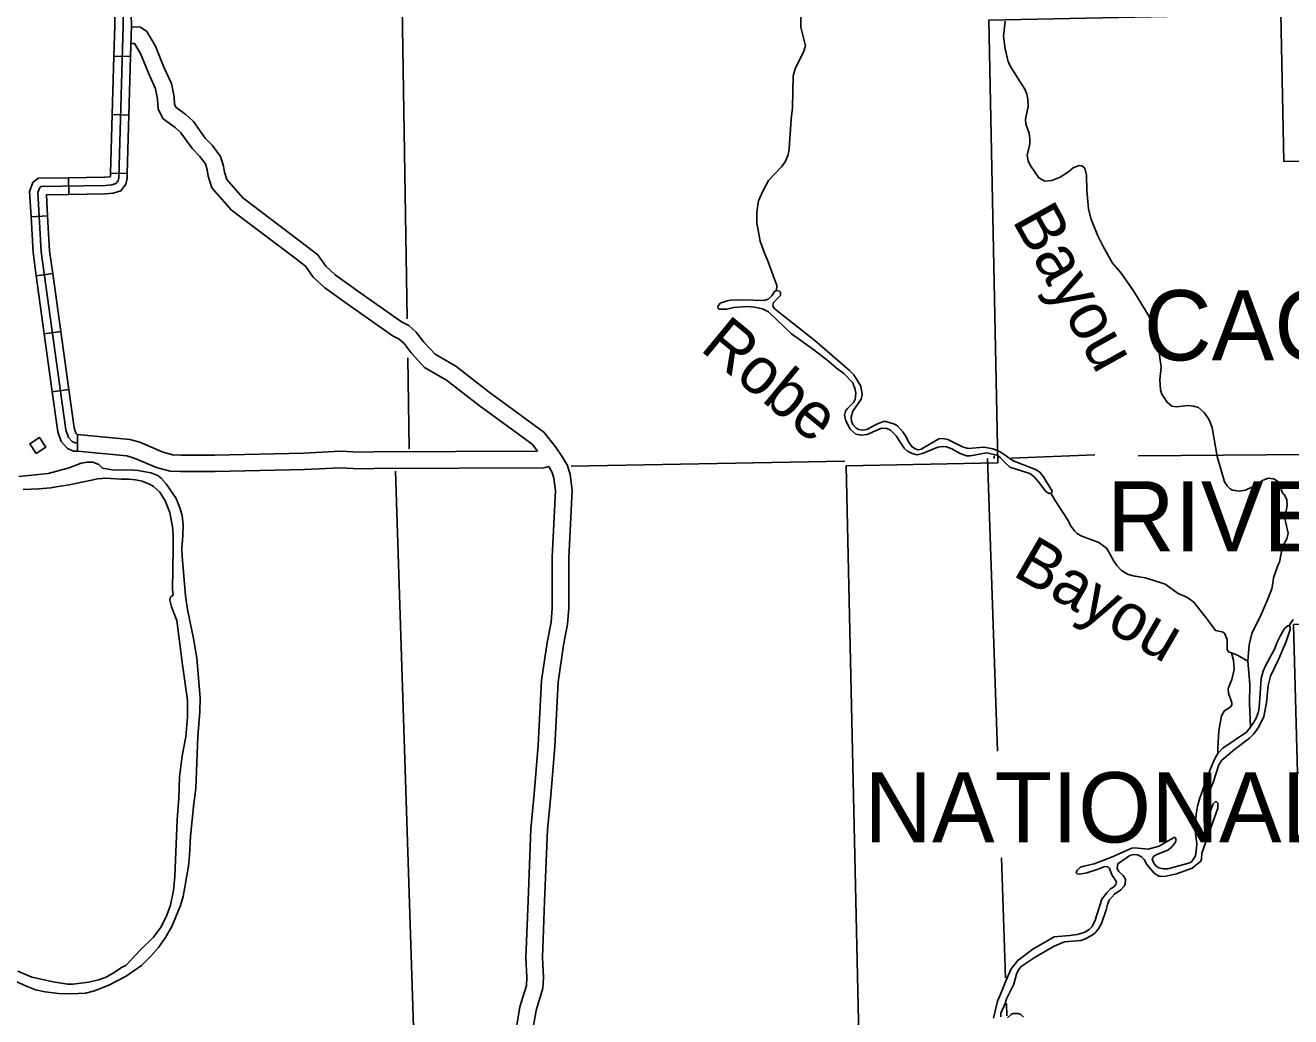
# Model space of a CAD drawing. Extents: x 1084508 to 1142749, y 1057638 to 1093403.
# Drawn here: x 1090132 to 1093716, y 1065503 to 1068310 of the extents above; entities that cross this region are included whole.
import ezdxf

# ---------------------------------------------------------------- set-up
doc = ezdxf.new("R2010")
doc.units = 0
for name, color, linetype in [('Level 32', 7, 'Continuous'), ('Level 35', 7, 'Continuous'), ('Level 4', 7, 'Continuous'), ('Level 46', 7, 'Continuous'), ('Level 5', 7, 'Continuous'), ('Level 56', 7, 'Continuous'), ('Level 7', 7, 'Continuous'), ('Level 9', 7, 'Continuous')]:
    doc.layers.add(name, color=color, linetype=linetype)

msp = doc.modelspace()

# ---------------------------------------------------------------- linework, layer by layer
at = {"layer": 'Level 32'}
for p, q in [((1090430.4, 1068221.7), (1090383.4, 1068223.1)), ((1090425.7, 1068056.1), (1090378.6, 1068057.4)), ((1090421, 1067890.4), (1090373.9, 1067891.8)), ((1090255.6, 1067831.5), (1090254.8, 1067878.5)), ((1090195.5, 1067770.4), (1090148.5, 1067767.7)), ((1090210, 1067607.3), (1090163.4, 1067600.8)), ((1090232.8, 1067443.1), (1090186.2, 1067436.7)), ((1090255.6, 1067279), (1090208.9, 1067272.5)), ((1090280.3, 1067151.7), (1090279.9, 1067104.6))]:
    msp.add_line(p, q, dxfattribs=at)
for points in [[(1090280.1, 1067128.2), (1090273.5, 1067128.2), (1090265.5, 1067131.4), (1090255, 1067143.5), (1090247.6, 1067164.9), (1090177.7, 1067669.1), (1090168.1, 1067836.7), (1090173.2, 1067850.7), (1090177.1, 1067853.7), (1090358.2, 1067856.7), (1090377, 1067858.4), (1090389, 1067862), (1090395, 1067870.1), (1090397.1, 1067879.6), (1090409.4, 1068309.7), (1090407.2, 1068407.1)], [(1090383.4, 1068223.1), (1090385.8, 1068309.8), (1090384.6, 1068366.1)], [(1090430.4, 1068221.7), (1090432.9, 1068309.6), (1090431.6, 1068369.5)], [(1090378.6, 1068057.4), (1090383.4, 1068223.1)], [(1090425.7, 1068056.1), (1090430.4, 1068221.7)], [(1090373.9, 1067891.8), (1090378.6, 1068057.4)], [(1090421, 1067890.4), (1090425.7, 1068056.1)], [(1090254.8, 1067878.5), (1090357, 1067880.2), (1090372.5, 1067881.6), (1090373.5, 1067881.9), (1090373.7, 1067882.6), (1090373.9, 1067891.8)], [(1090255.6, 1067831.5), (1090359.5, 1067833.2), (1090381.4, 1067835.2), (1090403.3, 1067841.7), (1090416.9, 1067860.1), (1090420.6, 1067876.7), (1090421, 1067890.4)], [(1090148.5, 1067767.7), (1090144.3, 1067840.2), (1090153.4, 1067865.3), (1090169.1, 1067877.1), (1090254.8, 1067878.5)], [(1090195.5, 1067770.4), (1090192, 1067830.4), (1090255.6, 1067831.5)], [(1090163.4, 1067600.8), (1090154.2, 1067666.8), (1090148.5, 1067767.7)], [(1090210, 1067607.3), (1090201.1, 1067671.4), (1090195.5, 1067770.4)], [(1090186.2, 1067436.7), (1090163.4, 1067600.8)], [(1090232.8, 1067443.1), (1090210, 1067607.3)], [(1090208.9, 1067272.5), (1090186.2, 1067436.7)], [(1090255.6, 1067279), (1090232.8, 1067443.1)], [(1090280.3, 1067151.7), (1090279.1, 1067151.7), (1090275.8, 1067155.5), (1090270.6, 1067170.5), (1090255.6, 1067279)], [(1090279.9, 1067104.6), (1090268.9, 1067104.7), (1090251.5, 1067111.6), (1090234.3, 1067131.6), (1090224.6, 1067159.4), (1090208.9, 1067272.5)]]:
    msp.add_lwpolyline(points, dxfattribs=at)
at = {"layer": 'Level 35'}
for points in [[(1092329.3, 1068346.6), (1092328.7, 1068305.4), (1092342, 1068252.3), (1092337, 1068234.3), (1092313.6, 1068190.1), (1092306.8, 1068167.6), (1092305.3, 1068077), (1092301.3, 1068045.1), (1092296.2, 1067960.3), (1092293, 1067943.2), (1092284.3, 1067923.4), (1092274.4, 1067909.6), (1092237, 1067871.3), (1092221.1, 1067840.9), (1092209.1, 1067813.5), (1092204.5, 1067780.9), (1092204.6, 1067750.1), (1092214.1, 1067698.9), (1092225.1, 1067667.8), (1092236.9, 1067640.2), (1092261.4, 1067573.1), (1092259.6, 1067559.8)], [(1092908.2, 1068322.1), (1092902.7, 1068279.5), (1092907.9, 1068243.5), (1092916.6, 1068207.3), (1092925.3, 1068189.4), (1092963.3, 1068129.9), (1092969.1, 1068115), (1092972, 1068101), (1092972.7, 1068080.3), (1092965.7, 1068045.1), (1092966.2, 1068030.7), (1092975.4, 1068004.9), (1092977.8, 1067989.9), (1092977.3, 1067975.1), (1092969.6, 1067943.1), (1092972.6, 1067926.8), (1092979, 1067914.8), (1093002.7, 1067878.1), (1093020.5, 1067869.3), (1093040.2, 1067870.9), (1093063.1, 1067880.7), (1093087.1, 1067895.7), (1093099.9, 1067907.1), (1093117.2, 1067913.6), (1093124.5, 1067912), (1093133.4, 1067905.4), (1093138.5, 1067885.7), (1093138.9, 1067842.7), (1093144, 1067790.6), (1093150.5, 1067763.2), (1093170.3, 1067713.8), (1093184.1, 1067685.7), (1093211.3, 1067636.9), (1093236.1, 1067608.4), (1093271.2, 1067558), (1093315.8, 1067485.9), (1093328.9, 1067448), (1093335.3, 1067416.8), (1093341.6, 1067395.6), (1093349.3, 1067342.7), (1093345.4, 1067306.4), (1093347.3, 1067277.9), (1093351.4, 1067266)], [(1093039.8, 1066986.4), (1093032.7, 1066984.3), (1093022.8, 1066990.2), (1093002.1, 1067017.5), (1092989.1, 1067032.2), (1092977.6, 1067040.9), (1092921.2, 1067058.9), (1092902.8, 1067075.6), (1092893.7, 1067086), (1092885, 1067093.2), (1092855, 1067099.8), (1092809.5, 1067091.4), (1092798, 1067091.3), (1092779.9, 1067098), (1092756.3, 1067111.3), (1092742, 1067116.2), (1092730.1, 1067117.1), (1092717, 1067115.7), (1092674, 1067097.3), (1092658.1, 1067094.3), (1092644.5, 1067097.6), (1092631.4, 1067104.7), (1092621.5, 1067113.2), (1092599, 1067148), (1092582.5, 1067164.1), (1092572.4, 1067168.5), (1092557.3, 1067169.3), (1092516.5, 1067151.9), (1092499.7, 1067149.2), (1092485.1, 1067152.8), (1092469, 1067166.4), (1092456.6, 1067190.5), (1092453, 1067206.1), (1092455.8, 1067217.5), (1092461.2, 1067225.6), (1092478.2, 1067242.2), (1092482.9, 1067250.5), (1092485.2, 1067268.8), (1092483.3, 1067278.8), (1092476.4, 1067297.7), (1092450.8, 1067324.3), (1092429.3, 1067339.9), (1092407.3, 1067359.6), (1092365.6, 1067391.6), (1092302.4, 1067436.4), (1092237.4, 1067499), (1092220.8, 1067507.3), (1092198.1, 1067512.2), (1092177.1, 1067514.3), (1092138.3, 1067511.2), (1092119.3, 1067506.8), (1092099, 1067506.1), (1092095.1, 1067508.5), (1092094.3, 1067514.4), (1092100.9, 1067523.2), (1092117.4, 1067529), (1092130.1, 1067531.7), (1092164.9, 1067533.4), (1092224.8, 1067530.7), (1092236.3, 1067534.5), (1092247.2, 1067544.6), (1092254.4, 1067556.5), (1092259.6, 1067559.8)], [(1092259.6, 1067559.8), (1092268.4, 1067557.6), (1092271, 1067555.1), (1092271, 1067545.4), (1092251.9, 1067525.6), (1092249.3, 1067518.3), (1092251, 1067513.3), (1092256, 1067506.9), (1092274.9, 1067491.4), (1092368.8, 1067418.1), (1092466.8, 1067333), (1092478.8, 1067320.2), (1092498.9, 1067288.4), (1092502.8, 1067265), (1092499.8, 1067252), (1092476.5, 1067217.6), (1092471.4, 1067200.4), (1092472.4, 1067189.1), (1092476.7, 1067180.2), (1092485.5, 1067169.8), (1092492.9, 1067165.3), (1092503.3, 1067163.4), (1092516.1, 1067165.4), (1092544.7, 1067180.8), (1092563, 1067188), (1092569.8, 1067188.2), (1092594.5, 1067181.2), (1092603.1, 1067176.4), (1092618.1, 1067159), (1092627.7, 1067144.5), (1092634.1, 1067130.6), (1092643, 1067117.1), (1092653.2, 1067110.5), (1092661.7, 1067107.9), (1092670.1, 1067109.8), (1092719.7, 1067138.8), (1092731.5, 1067139.8), (1092745.1, 1067137.1), (1092758.5, 1067130.9), (1092786.8, 1067116.4), (1092802.9, 1067112.2), (1092847.6, 1067115.9), (1092873.8, 1067110.8), (1092893.5, 1067102.3), (1092929, 1067078.3), (1092942.7, 1067071.9), (1092993.5, 1067052.8), (1093005.7, 1067044.7), (1093016.4, 1067032.1), (1093040.6, 1066991.4), (1093039.8, 1066986.4)], [(1093351.4, 1067266), (1093366.6, 1067243), (1093380.1, 1067232.1), (1093393.3, 1067230.3), (1093424.8, 1067233.6), (1093441.5, 1067231.9), (1093455.4, 1067227.6), (1093471.5, 1067213.7), (1093484.4, 1067194.9), (1093494.5, 1067171.7), (1093507.8, 1067088.8), (1093528.6, 1067017.8), (1093536.2, 1067005.8), (1093544.6, 1066997.6), (1093551.6, 1066994), (1093570.5, 1066990.9), (1093588.6, 1066993.7), (1093610.2, 1067003.8), (1093636.9, 1067021.3), (1093652.7, 1067027.8), (1093667.5, 1067026.1), (1093678.3, 1067020.2), (1093685.8, 1067010.4), (1093690.2, 1066992.9), (1093694.5, 1066984.6), (1093699, 1066980.6), (1093705.7, 1066966.7), (1093706.6, 1066950), (1093699.9, 1066913.4), (1093709.4, 1066871.9), (1093705.8, 1066855.7), (1093696.4, 1066838.7), (1093692.6, 1066829.5), (1093684.4, 1066790.2), (1093680.4, 1066780.3), (1093667.4, 1066746), (1093666, 1066730.2), (1093662.7, 1066714.7), (1093649.2, 1066678.1), (1093631.6, 1066640.1), (1093606.3, 1066588), (1093598.9, 1066556), (1093595.4, 1066509.4), (1093600.6, 1066444.8), (1093599.8, 1066389.4), (1093602.9, 1066322.5)], [(1093548.5, 1066533.6), (1093540.3, 1066535.9), (1093536.3, 1066543), (1093536.4, 1066570.6), (1093528.9, 1066588.9), (1093522.2, 1066592.8), (1093503.3, 1066596.6), (1093482.9, 1066625.2), (1093441.8, 1066676.3), (1093421.9, 1066691.1), (1093397.4, 1066701.3), (1093360.5, 1066727.4), (1093323.5, 1066740), (1093304.5, 1066745.4), (1093269.9, 1066750.9), (1093254.3, 1066756.3), (1093237.7, 1066766.5), (1093224.1, 1066780.5), (1093215.9, 1066792.5), (1093203.5, 1066815.7), (1093194.3, 1066829.2), (1093173.1, 1066845.8), (1093125.2, 1066863.4), (1093112.8, 1066870.5), (1093104.1, 1066878.4), (1093094.6, 1066890.7), (1093084.5, 1066910.5), (1093047.3, 1066967.1), (1093037.3, 1066985)], [(1093329.9, 1065935.3), (1093335.7, 1065928.9), (1093343.4, 1065923.8), (1093355.7, 1065921.4), (1093368.2, 1065921.8), (1093430.4, 1065938.6), (1093436.2, 1065942.6), (1093445.8, 1065956.4), (1093448.1, 1065962.5), (1093450.3, 1065991.8), (1093445.9, 1066029.4), (1093448.8, 1066076.6), (1093452.5, 1066099.1), (1093458.1, 1066118.7), (1093480.8, 1066184.3), (1093500.2, 1066231.7), (1093510.4, 1066247.8), (1093524.6, 1066262.7), (1093590.9, 1066308.3), (1093602.9, 1066322.5), (1093617.5, 1066346.3), (1093624.8, 1066363.2), (1093627.2, 1066377.7), (1093633, 1066460), (1093638.6, 1066481.2), (1093644.7, 1066496.8), (1093671.6, 1066545.8), (1093676.8, 1066561.1), (1093686.2, 1066580.6), (1093699, 1066601.7), (1093708.4, 1066609.9), (1093712.5, 1066610.7), (1093714.8, 1066605.7), (1093715, 1066598.8), (1093703.9, 1066564.8), (1093682, 1066514.4), (1093659.4, 1066467.1), (1093653.1, 1066440.2), (1093648, 1066391.3), (1093640.2, 1066352.7), (1093626.4, 1066323.3), (1093611.7, 1066303.6), (1093599.6, 1066291.3), (1093557.3, 1066259.7), (1093521.3, 1066228.7), (1093513, 1066216.4), (1093498.2, 1066168.5), (1093479.3, 1066122.3), (1093476, 1066109.3), (1093474.6, 1066094.8)], [(1093712.5, 1066610.7), (1093723.2, 1066628)], [(1093595.4, 1066509.4), (1093566, 1066526.3), (1093548.5, 1066533.6), (1093554.9, 1066512.1), (1093556, 1066486.4), (1093550, 1066457.9), (1093539.6, 1066431.8), (1093540, 1066418.9), (1093549.3, 1066391.8), (1093549.5, 1066385.2), (1093545.9, 1066379.8), (1093528.1, 1066368.2), (1093520.7, 1066354.4), (1093512.7, 1066312), (1093510.2, 1066263.2), (1093510.4, 1066247.8)], [(1093474.6, 1066094.8), (1093471.7, 1066075.2), (1093474.8, 1066068.7), (1093479.8, 1066067.6), (1093483.8, 1066070.9), (1093497.1, 1066105.9), (1093503.2, 1066111.7), (1093506, 1066111.2), (1093509.9, 1066107.2), (1093509.7, 1066092.8), (1093465.2, 1065965.9), (1093464.2, 1065949.2), (1093461.9, 1065943.4), (1093437.8, 1065923.4), (1093392.8, 1065907.5), (1093358.6, 1065899.5), (1093342.9, 1065900.8), (1093329.5, 1065908.9), (1093309, 1065933.4), (1093301, 1065947.9), (1093294.1, 1065955.8), (1093282.4, 1065961.4), (1093272, 1065962), (1093260.5, 1065958.8), (1093227.1, 1065936), (1093225, 1065923.1), (1093228.7, 1065915), (1093242.3, 1065902.3), (1093248.2, 1065891.8), (1093247.7, 1065877.9), (1093245.1, 1065872.2), (1093235.1, 1065861.5), (1093217, 1065849.6), (1093202.5, 1065832.4), (1093197.3, 1065820.6), (1093194, 1065805.7), (1093180.5, 1065766.6), (1093173.1, 1065753.5), (1093164.4, 1065742.2), (1093156.7, 1065735.6), (1093135.5, 1065723.3), (1093121.6, 1065718.8), (1093075.9, 1065714.8), (1093046.9, 1065702.5), (1092993, 1065670.9), (1092953.5, 1065644.4), (1092945.3, 1065635), (1092939.4, 1065622.9), (1092931.9, 1065594.7), (1092911.3, 1065552.8), (1092907.6, 1065540.4), (1092895.3, 1065513), (1092895.7, 1065502.3)], [(1092874.5, 1065498.1), (1092885.8, 1065546.3), (1092895.7, 1065568.6), (1092910.5, 1065606.5), (1092924.5, 1065638.4), (1092943.8, 1065661.7), (1092986.3, 1065694.2), (1093046.3, 1065728.9), (1093090.7, 1065732.2), (1093111.9, 1065735.8), (1093131.5, 1065741.1), (1093145.6, 1065749.4), (1093154.4, 1065758.2), (1093162.7, 1065775.8), (1093182, 1065835.5), (1093195.3, 1065853.6), (1093205.9, 1065864.3), (1093214.2, 1065869.3), (1093220.8, 1065877.4), (1093222.8, 1065884.3), (1093209.6, 1065904), (1093203.4, 1065923), (1093197.9, 1065927.5), (1093190, 1065928.2), (1093168.4, 1065919.7), (1093138.9, 1065910.5), (1093119, 1065906.4), (1093111.4, 1065907.1), (1093108.5, 1065910.1), (1093111.7, 1065917.8), (1093121.2, 1065925.7), (1093134.5, 1065930.2), (1093159.4, 1065935.7), (1093209, 1065954), (1093266.4, 1065980.1), (1093273.9, 1065981), (1093312.9, 1065977.2), (1093344.2, 1065985.8), (1093376.2, 1066004.4), (1093388.3, 1066010.8), (1093390.8, 1066008.7), (1093391.1, 1065999.9), (1093388.2, 1065994.1), (1093378.5, 1065982.5), (1093368.1, 1065974.6), (1093336.9, 1065962.3), (1093327.6, 1065956.3), (1093324.4, 1065949), (1093329.9, 1065935.3)], [(1092914.3, 1065499.1), (1092924.6, 1065508.9), (1092930.8, 1065511.6), (1092943.3, 1065511.4), (1092951.9, 1065509.2), (1092959.3, 1065500.9)]]:
    msp.add_lwpolyline(points, dxfattribs=at)
at = {"layer": 'Level 4'}
for points in [[(1092453.6, 1067076), (1091678.8, 1067061.7)], [(1093161.4, 1067094), (1092924.5, 1067084.4)], [(1094128.2, 1067097.6), (1093284.9, 1067090.8)]]:
    msp.add_lwpolyline(points, dxfattribs=at)
at = {"layer": 'Level 46'}
for points in [[(1091568.4, 1065455.9), (1091579.1, 1065519.9), (1091598.5, 1065583), (1091600.3, 1065614.1), (1091597.1, 1065669.9), (1091603.4, 1065829.1), (1091611.3, 1066031.6), (1091620.8, 1066129.5), (1091631.9, 1066268.1), (1091641.4, 1066449.9), (1091657.1, 1066554.7), (1091668.3, 1066614.3), (1091671.7, 1066659.3), (1091671.7, 1066802.4), (1091681.2, 1066994.3), (1091676, 1067038.1), (1091668.1, 1067063.6), (1091653.7, 1067087.2), (1091633.9, 1067116.9), (1091601.1, 1067158.3), (1091446.1, 1067271), (1091351.5, 1067344.8), (1091292.9, 1067378.7), (1091261.2, 1067413.4), (1091239.9, 1067441.2), (1091218.5, 1067460.7), (1091198.1, 1067470.9), (1091077.5, 1067555.5), (1091010.4, 1067603.9), (1090983.2, 1067628.3), (1090960.6, 1067660.7), (1090929.1, 1067685.2), (1090748.4, 1067822), (1090702.7, 1067873.4), (1090696.6, 1067894.2), (1090693.4, 1067911.5), (1090685.5, 1067939.2), (1090661.4, 1067970.7), (1090642.1, 1067991.1), (1090608.3, 1068037.8), (1090586.6, 1068057.7), (1090559.7, 1068077.6), (1090555.1, 1068085.9), (1090553.8, 1068107.5), (1090546.6, 1068145.2), (1090525, 1068191.8), (1090500.8, 1068251.4), (1090476.4, 1068292.7), (1090458.9, 1068304.9), (1090436.2, 1068306.4), (1090433, 1068306.3)], [(1091583.5, 1067104.6), (1091568.2, 1067124), (1091417.7, 1067233.4), (1091325.1, 1067305.7), (1091263.1, 1067341.6), (1091225.1, 1067383.1), (1091205.1, 1067409.3), (1091191.6, 1067421.5), (1091173.9, 1067430.4), (1091050.2, 1067517.2), (1090980.9, 1067567.2), (1090947.8, 1067596.8), (1090926, 1067627.9), (1090900.4, 1067647.8), (1090716.3, 1067787.2), (1090660.5, 1067850.1), (1090650.7, 1067883.3), (1090647.5, 1067900.8), (1090642.7, 1067917.7), (1090625.5, 1067940.1), (1090605.8, 1067961), (1090573, 1068006.3), (1090556.6, 1068021.3), (1090523.3, 1068045.9), (1090508.8, 1068072.5), (1090507, 1068101.7), (1090501.4, 1068130.7), (1090481.8, 1068173), (1090458.4, 1068230.8), (1090441.7, 1068258.9), (1090435.7, 1068259.3), (1090431.5, 1068259.1)], [(1090280.3, 1067151.7), (1090428.1, 1067137.2), (1090456.5, 1067129.5), (1090519.8, 1067102.3), (1090549.7, 1067094.4), (1090572.6, 1067093.4), (1090669.2, 1067093.4), (1090921, 1067099), (1091023.8, 1067104.7), (1091079.6, 1067101.3), (1091119.6, 1067102.4), (1091583.5, 1067104.6)], [(1090279.9, 1067104.6), (1090419.5, 1067090.8), (1090441, 1067084.9), (1090504.4, 1067057.7), (1090542.5, 1067047.5), (1090571.6, 1067046.3), (1090669.7, 1067046.3), (1090922.8, 1067052), (1091023.7, 1067057.6), (1091078.8, 1067054.2), (1091120.4, 1067055.3), (1091600.8, 1067057.6), (1091614.8, 1067060.5)], [(1091521.6, 1065461.4), (1091533.1, 1065530.7), (1091551.8, 1065591.4), (1091553.1, 1065614.2), (1091550, 1065669.5), (1091556.4, 1065831), (1091564.3, 1066034.8), (1091573.9, 1066133.7), (1091585, 1066271.3), (1091594.5, 1066454.6), (1091610.6, 1066562.5), (1091621.6, 1066620.4), (1091624.6, 1066661), (1091624.6, 1066803.6), (1091634, 1066992.7), (1091629.8, 1067028.3), (1091624.9, 1067044), (1091614.8, 1067060.5)]]:
    msp.add_lwpolyline(points, dxfattribs=at)
at = {"layer": 'Level 5'}
for points in [[(1091199, 1068421.8), (1091214, 1067479)], [(1091215.7, 1067369.1), (1091219.8, 1067110.5)], [(1092886.3, 1066254.4), (1092857.3, 1067083.5)], [(1092876.9, 1067091.1), (1092877, 1067083.9)], [(1091181.1, 1067047.5), (1091235.4, 1065356.4)], [(1092908.8, 1065612.3), (1092896.9, 1065953)], [(1092912.6, 1065505.2), (1092911.4, 1065539.8)]]:
    msp.add_lwpolyline(points, dxfattribs=at)
at = {"layer": 'Level 56'}
msp.add_lwpolyline([(1090162.8, 1067097.7), (1090144.8, 1067125), (1090172.2, 1067143.1), (1090190.2, 1067115.8)], close=True, dxfattribs=at)
at = {"layer": 'Level 7'}
msp.add_lwpolyline([(1092099.4, 1064749.4), (1092099.1, 1064749.5), (1092081.8, 1065357.6), (1092494.9, 1065363.5), (1092457.7, 1067062.4), (1092886.8, 1067071), (1092861.5, 1068325.5), (1093688.5, 1068342.2), (1093697.2, 1067924.4), (1094326.3, 1067932), (1094350.2, 1067088.1), (1094127.7, 1067083.7), (1094136.3, 1066704.3), (1093926.7, 1066715.6), (1093944.2, 1066617.4), (1093724.5, 1066613.3), (1093735.8, 1066191.9), (1094527.2, 1066205.6), (1094540.5, 1065419.5)], dxfattribs=at)
at = {"layer": 'Level 9'}
for points in [[(1090351, 1067056.4), (1090340.4, 1067066.7), (1090323.3, 1067072.8), (1090307.9, 1067073.2), (1090291, 1067070.8), (1090257, 1067056.8), (1090197.1, 1067041.5)], [(1090197.1, 1067041.5), (1090114.2, 1067032.6)], [(1090444.2, 1067023.3), (1090425.7, 1067025.2), (1090403.4, 1067025.4), (1090360.4, 1067028.1), (1090337.9, 1067026.4), (1090256.7, 1067008.6), (1090219.9, 1067003.7), (1090204.4, 1067000.6)], [(1090452, 1067049.7), (1090431.5, 1067051.4), (1090420.2, 1067050.2), (1090378.8, 1067051), (1090351, 1067056.4)], [(1090575.8, 1066826.1), (1090575.8, 1066829.8), (1090578.8, 1066864.2), (1090579.3, 1066895.6), (1090576.6, 1066922), (1090569.9, 1066944.1), (1090559.4, 1066970.1), (1090531.1, 1067012), (1090516.8, 1067027.5), (1090507.8, 1067035.6), (1090488.3, 1067043.3), (1090452, 1067049.7)], [(1090204.4, 1067000.6), (1090171, 1066997.4), (1090126.4, 1066995.7)], [(1090550.7, 1066828.6), (1090551.4, 1066868), (1090549.4, 1066890.3), (1090541.5, 1066930.6), (1090528.9, 1066963.5), (1090513.4, 1066988.1), (1090495.9, 1067003.9), (1090484.5, 1067010.4), (1090463.2, 1067019.5), (1090444.2, 1067023.3)], [(1090069.1, 1065619.4), (1090137.5, 1065587.7), (1090160.9, 1065579), (1090188.4, 1065572.7), (1090226.8, 1065568.6), (1090261.9, 1065566.9), (1090302.9, 1065568.9), (1090328.4, 1065575.4), (1090369.2, 1065591.5), (1090417.9, 1065617), (1090461.1, 1065647.3), (1090488.2, 1065673.7), (1090509.3, 1065698.6), (1090529.4, 1065727.2), (1090547.8, 1065758.3), (1090571.9, 1065817.6), (1090579.9, 1065843), (1090595, 1065928.7), (1090597.2, 1065958.7), (1090599.8, 1066013.8), (1090609.4, 1066106.2), (1090615.8, 1066148.6), (1090620.8, 1066296.2), (1090626.4, 1066366.2), (1090627.6, 1066405.5), (1090618.1, 1066518.1), (1090608.8, 1066573.8), (1090592, 1066655.9), (1090586, 1066695.3), (1090576.2, 1066806.3), (1090575.8, 1066826.1)], [(1090111, 1065631.5), (1090151.3, 1065614.2), (1090211.6, 1065601.1), (1090252.2, 1065594.9), (1090267.3, 1065594.5), (1090312.2, 1065600), (1090339.9, 1065606.6), (1090361.3, 1065614.8), (1090379.4, 1065624.5), (1090406.4, 1065642.7), (1090417.2, 1065647.8), (1090456.6, 1065690), (1090495.2, 1065728), (1090517.5, 1065757.3), (1090533.3, 1065789.9), (1090543.4, 1065818.9), (1090551.8, 1065860.3), (1090556.1, 1065900.1), (1090562.9, 1066060.1), (1090567.5, 1066121.5), (1090569.4, 1066180.7), (1090576.2, 1066241.9), (1090586.7, 1066295.1), (1090591.4, 1066352.1), (1090592.1, 1066399), (1090577.6, 1066499.2), (1090561.7, 1066625), (1090546.3, 1066663.8), (1090542, 1066681.9), (1090543.3, 1066690.5), (1090549.7, 1066695.1), (1090551.2, 1066698), (1090549.2, 1066712.3), (1090550.7, 1066828.6)]]:
    msp.add_lwpolyline(points, dxfattribs=at)

# ---------------------------------------------------------------- texts
at = {"layer": 'Level 35'}
for s, rotation, p in [('Bayou', 299.0547, (1092926.3, 1067757.9)), ('Robe', 320.4865, (1092040.5, 1067391.8)), ('Bayou', 329.9414, (1092925.6, 1066754))]:
    msp.add_text(s, height=132.58, rotation=rotation, dxfattribs=at).set_placement(p)
at = {"layer": 'Level 7'}
for s, p in [('CACHE', (1093300.5, 1067361.4)), ('RIVER', (1093196, 1066820.3)), ('NATIONAL', (1092508.6, 1065996.2))]:
    msp.add_text(s, height=198.88, dxfattribs=at).set_placement(p)

doc.saveas('drawing.dxf')
